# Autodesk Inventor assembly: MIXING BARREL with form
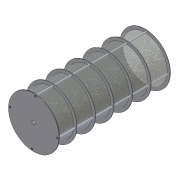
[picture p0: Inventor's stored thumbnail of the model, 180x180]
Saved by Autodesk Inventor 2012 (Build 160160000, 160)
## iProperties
RuleStatus: InUse
Created: 2011-05
Part Number: MIXING BARREL with form
Document SubType Name: Assembly
Designer: Dimitris
Author: Dimitris
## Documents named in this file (9)
- C:\CMU_Update\Week 5 - Inventor Design Automation\Projects\Files\iLogic\MIXING BARREL with form.iam
- C:\CMU_Update\Week 5 - Inventor Design Automation\Projects\Files\iLogic\Parts\PERFORATED METAL SHEET.ipt
- C:\CMU_Update\Week 5 - Inventor Design Automation\Projects\Files\iLogic\Parts\OUTSIDE FLANGE RING.ipt
- C:\CMU_Update\Week 5 - Inventor Design Automation\Projects\Files\iLogic\Parts\INSIDE FLANGE RING.ipt
- C:\CMU_Update\Week 5 - Inventor Design Automation\Projects\Files\iLogic\Parts\OUTSIDE ROD.ipt
- C:\CMU_Update\Week 5 - Inventor Design Automation\Projects\Files\iLogic\Parts\BLIND FLANGE.ipt
- C:\CMU_Update\Week 5 - Inventor Design Automation\Projects\Files\iLogic\Libraries\Content Center Files\R2012\en-US\ASME ANSI B18.3.5M(2)\ASME_ANSI B18.3.5M - M10x16(2).ipt
- C:\CMU_Update\Week 5 - Inventor Design Automation\Projects\Files\iLogic\Libraries\Content Center Files\R2012\en-US\IFI 542(1)\IFI 542 - 12(1).ipt
- C:\CMU_Update\Week 5 - Inventor Design Automation\Projects\Files\iLogic\Libraries\Content Center Files\R2012\en-US\ANSI B18.3.1M(1)\ANSI B18.3.1M - M10x1.5 x 20(2).ipt
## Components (25 placed, 8 different names)
1. PERFORATED METAL SHEET:1 — Insert:1, Insert:2, Insert:3
2. OUTSIDE FLANGE RING:1 — Insert:1, Insert:6, Insert:10
3. OUTSIDE FLANGE RING:2 — Insert:2, Mate:4
4. BLIND FLANGE:1 — Insert:10, Mate:2
5. OUTSIDE ROD:1 — Insert:6, Mate:2, Mate:3, Mate:4
6. Broached Hexagon Socket Flat Countersunk Head Cap Screws - Metric M10x16:1
7. Circular Washer (Metric) (IFI) 12:1
8. Broached Socket Head Cap Screw - Metric M10x1.5 x 20:1
9. OUTSIDE ROD:2
10. Broached Hexagon Socket Flat Countersunk Head Cap Screws - Metric M10x16:2
11. Circular Washer (Metric) (IFI) 12:2
12. Broached Socket Head Cap Screw - Metric M10x1.5 x 20:2
13. OUTSIDE ROD:3
14. Broached Hexagon Socket Flat Countersunk Head Cap Screws - Metric M10x16:3
15. Circular Washer (Metric) (IFI) 12:3
16. Broached Socket Head Cap Screw - Metric M10x1.5 x 20:3
17. OUTSIDE ROD:4
18. Broached Hexagon Socket Flat Countersunk Head Cap Screws - Metric M10x16:4
19. Circular Washer (Metric) (IFI) 12:4
20. Broached Socket Head Cap Screw - Metric M10x1.5 x 20:4
21. INSIDE FLANGE RING:1 — Insert:3, Mate:3
22. INSIDE FLANGE RING:2
23. INSIDE FLANGE RING:3
24. INSIDE FLANGE RING:4
25. INSIDE FLANGE RING:5
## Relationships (8: Insert 5, Mate 3)
- Insert:1: PERFORATED METAL SHEET:1 ↔ OUTSIDE FLANGE RING:1
- Insert:2: PERFORATED METAL SHEET:1 ↔ OUTSIDE FLANGE RING:2
- Insert:3: PERFORATED METAL SHEET:1 ↔ INSIDE FLANGE RING:1
- Insert:6: OUTSIDE FLANGE RING:1 ↔ OUTSIDE ROD:1
- Insert:10: OUTSIDE FLANGE RING:1 ↔ BLIND FLANGE:1
- Mate:2: BLIND FLANGE:1 ↔ OUTSIDE ROD:1
- Mate:3: OUTSIDE ROD:1 ↔ INSIDE FLANGE RING:1
- Mate:4: OUTSIDE FLANGE RING:2 ↔ OUTSIDE ROD:1
